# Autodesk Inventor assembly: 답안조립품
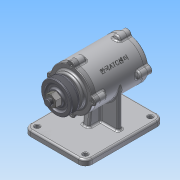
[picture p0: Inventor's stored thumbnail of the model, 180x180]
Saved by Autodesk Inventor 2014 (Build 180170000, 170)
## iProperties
Created: 2015-12
Part Number: 답안조립품
Document SubType Name: Assembly
Designer: net
Author: net
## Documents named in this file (11)
- C:\Users\net\Desktop\451207v1037\답안조립품.iam
- C:\Users\net\Desktop\451207v1037\본체.ipt
- C:\Users\net\Desktop\451207v1037\축.ipt
- C:\Users\net\Desktop\451207v1037\베어링 6204.ipt
- C:\Users\net\Desktop\451207v1037\키(4 x 4 x 12).ipt
- C:\Users\net\Desktop\451207v1037\커버2.ipt
- C:\Users\net\Desktop\451207v1037\커버.ipt
- C:\Users\net\Desktop\451207v1037\V-벨트풀리.ipt
- C:\Users\net\Desktop\451207v1037\너트 M12x1.25.ipt
- C:\Users\net\Desktop\451207v1037\오일실.ipt
- C:\Users\net\Desktop\451207v1037\볼트 M4 x 12.ipt
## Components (6 placed, 5 different names)
1. KS B 2023 6204 - 20 x 47 x 14:2
2. KS B 1311 (I) 4 x 4 x 12:1 — 각도:1, 각도:2
3. KS B 2023 6204 - 20 x 47 x 14:3
4. V-벨트풀리:1 — 각도:2
5. KS B 1012 클래스 1 일반 - 미터 M12x1.25:1
6. KS B 2804 D D - 20 32 8:1
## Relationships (2: Angle 2)
- 각도:1 [Angle]: KS B 1311 (I) 4 x 4 x 12:1
- 각도:2 [Angle]: KS B 1311 (I) 4 x 4 x 12:1 ↔ V-벨트풀리:1
